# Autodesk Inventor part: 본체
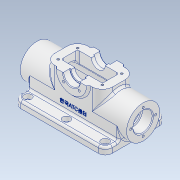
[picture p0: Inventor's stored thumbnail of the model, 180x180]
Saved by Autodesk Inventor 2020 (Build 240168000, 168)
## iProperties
Created: 2024-06
Part Number: 본체
Material: 알루미늄 6061
Document SubType Name: Modeling
Designer: oem
Density: 2.7 g/cm^3
Appearance: 알루미늄 - 평지
Mass: 551.511 g
Surface Area: 611.953 cm^2
Volume: 204.263 cm^3
Author: oem
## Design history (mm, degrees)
sketch "스케치3"
  geometry: L1 (0, 0)-(154, 0); L2 (0, 24)-(154, 24); L3 (0, 0)-(0, 24); L4 (154, 24)-(154, 0)
  constraints: 8 end point, 2 horizontal, 1 vertical
  dimensions: "d6" = 48 diameter of L2 L1; "d7" = 154 distance of L2.start L2.end; "d8" = 154 distance of L1.start L1.end
revolve "회전1" sketch "스케치3" stored, may be unused: angle "d9" = 90 deg
node "작업 평면1"
sketch "스케치4"
  geometry: L1 (-11, -44)-(-143, -44); L2 (-143, -44)-(-143, 44); L3 (-143, 44)-(-11, 44); L4 (-11, 44)-(-11, -44); L5 (0, -24)-(-154, -24) reference; 6 further points
  constraints: 8 end point, 3 midpoint, 2 parallel, 1 horizontal, 1 horizontal alignment, 1 perpendicular, 1 vertical alignment
  dimensions: "d11" = 132 distance of L1.start L1.end; "d12" = 88 distance of L3.end L1.start
extrude "돌출2" join sketch "스케치4" distance "d13" = 10; taper "d14" = 0 deg
node "작업 평면2"
sketch "스케치5"
  geometry: L1 (-35, -24)-(-119, -24); L2 (-119, -24)-(-119, 24); L3 (-119, 24)-(-35, 24); L4 (-35, 24)-(-35, -24); L5 (0, -24)-(-154, -24) reference; 6 further points
  constraints: 8 end point, 3 midpoint, 2 parallel, 1 coincident, 1 horizontal, 1 horizontal alignment, 1 perpendicular
  dimensions: "d16" = 84 distance of L1.start L1.end; "d17" = 48 distance of L3.end L1.start
extrude "돌출3" join sketch "스케치5" stored distance "d18" = 20; taper "d19" = 0 deg
sketch "스케치7"
  geometry: L1 (11, -15.875)-(11, -44) reference; L2 (143, -44)-(143, -15.875) reference; L3 (0, 24)-(154, 24) reference; L4 (0, -24)-(154, -24) reference; L5 (11, 44)-(11, -44) reference; L6 (143, -44)-(143, 44) reference; L7 (11, 24)-(143, 24); L8 (143, 24)-(143, -24); L9 (143, -24)-(11, -24); L10 (11, -24)-(11, 24); 4 further points
  constraints: 8 end point, 4 point on line, 2 parallel, 1 horizontal, 1 perpendicular
extrude "돌출5" join sketch "스케치7" stored distance "d28" = 10; taper "d29" = 0 deg
sketch "스케치9"
  geometry: L1 (119, 31)-(35, 31) reference; L2 (99, 31)-(55, 31); A1 r 22 centre (77, 31) between (99, 31) and (55, 31); 2 further points
  constraints: 2 end point, 2 point on circle, 2 point on line, 1 centre point, 1 coincident, 1 midpoint
  dimensions: "d33" = 44 diameter of A1
extrude "돌출7" join sketch "스케치9" stored distance "d34" = 54; taper "d35" = 0 deg
sketch "스케치10"
  geometry: L1 (55, 27)-(99, 27) reference; L2 (47, 12)-(107, 12); L3 (107, 12)-(107, -12); L4 (107, -12)-(47, -12); L5 (47, -12)-(47, 12); 4 further points
  constraints: 8 end point, 3 midpoint, 2 parallel, 1 horizontal, 1 horizontal alignment, 1 perpendicular, 1 vertical alignment
  dimensions: "d36" = 60 distance of L2.start L2.end; "d37" = 24 distance of L4.end L2.start
extrude "돌출8" cut sketch "스케치10" extent not by distance; stored distance "d38" = 0; taper "d39" = 0 deg
node "작업 평면3"
sketch "스케치11"
  geometry: L1 (9, -27)-(31, -27) reference; L2 (19, -27)-(19, -17); L3 (19, -17)-(21, -17); L4 (21, -17)-(21, 17); L5 (21, 17)-(19, 17); L6 (19, 17)-(19, 27); L7 (31, 27)-(9, 27) reference; L8 (31, -27)-(31, -24) reference; L9 (31, -27)-(31, 27); 2 further points
  constraints: 12 end point, 4 point on line, 3 perpendicular, 2 vertical
  dimensions: "d41" = 10 distance of L2.start L2.end; "d42" = 10 distance of L5.end L6.end; "d43" = 24 diameter of L6 L9; "d44" = 20 diameter of L4 L9
revolve "회전3" sketch "스케치11" stored, may be unused: angle "d45" = 90 deg
sketch "스케치12"
  geometry: L1 (0, -24)-(0, 24) reference; L2 (0, 14)-(15, 14); L3 (15, 14)-(15, 11); L4 (139, 11)-(139, 14); L5 (139, 14)-(154, 14); L6 (154, -24)-(154, 24) reference; L7 (0, 0)-(154, 0); L8 (15, 11)-(17, 11); L9 (17, 11)-(17, 18); L10 (17, 18)-(137, 18); L11 (137, 18)-(137, 11); L12 (137, 11)-(139, 11); A1 r 10 centre (77, 31) between (67, 31) and (87, 31) reference; 2 further points
  constraints: 20 end point, 5 perpendicular, 5 point on line, 2 horizontal, 2 midpoint, 1 point on circle, 1 vertical alignment
  dimensions: "d46" = 15 distance of L2.start L2.end; "d47" = 15 distance of L4.end L5.end; "d48" = 28 diameter of L2 L7; "d59" = 36 diameter of L10 L7; "d60" = 120 distance of L9.end L10.end; "d61" = 22 diameter of L12 L7
revolve "회전4" sketch "스케치12" stored, may be unused: angle "d50" = 90 deg
sketch "스케치13"
  geometry: L1 (107, 12)-(107, -12) reference; L2 (107, -12)-(47, -12) reference; L3 (47, -12)-(47, 12) reference; L4 (47, 12)-(107, 12) reference; L5 (11, -44)-(11, 44) reference; L6 (143, 44)-(143, -44) reference; L7 (17, 18)-(137, 18); L8 (137, 18)-(137, -18); L9 (137, -18)-(17, -18); L10 (17, -18)-(17, 18); L11 (143, 24)-(11, 24) reference; L12 (11, -24)-(143, -24) reference; 1 further point
  constraints: 8 end point, 2 parallel, 1 horizontal, 1 perpendicular
  dimensions: "d52" = 6 distance between parallel lines of L5 L10; "d54" = 6 distance between parallel lines of L6 L8; "d55" = 6 distance between parallel lines of L9 L12; "d56" = 6 distance between parallel lines of L11 L7
extrude "돌출9" cut sketch "스케치13" distance "d57" = 28; taper "d58" = 0 deg
fillet "모깎기1" dims "d62" = 10
sketch "스케치14"
  geometry: L1 (133, 44)-(21, 44) reference; A1 r 10 centre (21, 34) between (21, 44) and (11, 34) reference; A2 r 10 centre (133, 34) between (143, 34) and (133, 44) reference; A3 r 10 centre (21, -34) between (11, -34) and (21, -44) reference; A4 r 10 centre (133, -34) between (133, -44) and (143, -34) reference; 8 further points
  constraints: 4 coincident, 2 horizontal alignment, 2 vertical alignment, 1 midpoint
hole "구멍1" sketch "스케치14" at (133, 34), (77, 34), (21, 34), (21, -34), (77, -34), (133, -34) diameter "d63" = 6.6; stored, may be unused: countersink angle "d67" = 90 deg, drill point angle "d69" = 118 deg; dims "d64" = 11, "d65" = 11, "d66" = 6.6, "d68" = 8
sketch "스케치15"
  geometry: C1 r 14 at (0, 0) reference; C2 r 24 at (0, 0) reference; A1 r 18 centre (0, 0) between (0, 18) and (0, -18); 2 further points
  constraints: 3 point on circle, 2 vertical alignment, 1 centre point, 1 coincident, 1 horizontal alignment
  dimensions: "d70" = 36 diameter of A1
hole "구멍2" sketch "스케치15" at (0, 18), (0, -18), (18, 0), (-18, 0) diameter "d71" = 3.242; stored, may be unused: countersink angle "d75" = 82 deg, drill point angle "d77" = 118 deg; dims "d72" = 8, "d73" = 3.023, "d74" = 6.6, "d76" = 10
sketch "스케치16"
  geometry: C1 r 24 at (0, 0) reference; C2 r 1.621 at (0, -18) reference; A1 r 18 centre (0, 0) between (0, 18) and (18, 0); A2 r 18 centre (0, 0) between (18, 0) and (-18, 0) reference; 1 further point
  constraints: 2 coincident, 2 point on circle, 1 centre point
hole "구멍3" sketch "스케치16" at (0, 18), (18, 0), (0, -18), (-18, 0) diameter "d79" = 3.242; stored, may be unused: countersink angle "d83" = 82 deg, drill point angle "d85" = 118 deg; dims "d80" = 8, "d81" = 3.023, "d82" = 6.6, "d84" = 10
fillet "모깎기2" dims "d86" = 15
sketch "스케치17"
  geometry: L1 (45, -14)-(109, -14); L2 (109, -14)-(109, 14); L3 (109, 14)-(45, 14); L4 (45, 14)-(45, -14); L5 (65, 27)-(89, 27) reference; A1 r 15 centre (50, -9) between (35, -9) and (50, -24) reference; A2 r 15 centre (50, 9) between (50, 24) and (35, 9) reference; 8 further points
  constraints: 8 end point, 4 coincident, 3 midpoint, 2 parallel, 1 horizontal, 1 horizontal alignment, 1 perpendicular, 1 vertical alignment
  dimensions: "d87" = 64 distance of L2.end L3.end; "d88" = 28 distance of L3.end L1.start
fillet "모깎기3" dims "d89" = 3
hole "구멍4" sketch "스케치17" diameter "d90" = 3.242; stored, may be unused: countersink angle "d94" = 82 deg, drill point angle "d96" = 118 deg; dims "d91" = 8, "d92" = 3.023, "d93" = 6.6, "d95" = 10
sketch "스케치18"
  geometry: L1 (-77, 31)-(-77, 15); L2 (-77, 31)-(-88.314, 19.686); L3 (-77, 31)-(-65.686, 19.686); A1 r 22 centre (-77, 31) between (-99, 31) and (-55, 31) reference; A2 r 16 centre (-77, 31) between (-88.314, 19.686) and (-65.686, 19.686); 1 further point
  constraints: 6 end point, 3 point on circle, 1 centre point, 1 coincident, 1 vertical
  dimensions: "d97" = 32 diameter of A2; "d98" = 45 deg angle of L2 L1; "d99" = 45 deg angle of L3 L1
hole "구멍5" sketch "스케치18" at (-88.314, 19.686), (-65.686, 19.686) diameter "d100" = 3.242; stored, may be unused: countersink angle "d104" = 82 deg, drill point angle "d106" = 118 deg; dims "d101" = 8, "d102" = 3.023, "d103" = 6.6, "d105" = 10
sketch "스케치19"
  geometry: L1 (65.686, 19.686)-(77, 31); L2 (77, 31)-(88.314, 19.686); L3 (77, 31)-(77, 15); A1 r 22 centre (77, 31) between (55, 31) and (99, 31) reference; A2 r 16 centre (77, 31) between (65.686, 19.686) and (88.314, 19.686); 1 further point
  constraints: 6 end point, 3 point on circle, 1 centre point, 1 coincident, 1 vertical
  dimensions: "d107" = 32 diameter of A2; "d108" = 45 deg angle of L2 L3; "d109" = 45 deg angle of L1 L3
hole "구멍6" sketch "스케치19" at (65.686, 19.686), (88.314, 19.686) diameter "d110" = 3.242; stored, may be unused: countersink angle "d114" = 82 deg, drill point angle "d116" = 118 deg; dims "d111" = 8, "d112" = 3.023, "d113" = 6.6, "d115" = 10
fillet "모깎기4" dims "d117" = 0.3
fillet "모깎기5" dims "d118" = 3
fillet "모깎기6" dims "d119" = 3
fillet "모깎기7" dims "d120" = 3
fillet "모깎기8" dims "d121" = 3
chamfer "모따기1" distance "d122" = 1; stored, may be unused: second distance "d123" = 2, angle "d124" = 45 deg
chamfer "모따기2" distance "d125" = 1; stored, may be unused: second distance "d126" = 2, angle "d127" = 45 deg
fillet "모깎기9" dims "d128" = 3
fillet "모깎기10" dims "d129" = 3
sketch "스케치20"
  geometry: L1 (7, -13)-(119, -13) reference; A1 r 25 centre (63, 46) between (38, 46) and (88, 46) reference; 2 further points
  constraints: 1 vertical alignment, 1 other
  dimensions: "d130" = 20 distance from line of L1 point (63, 7)
feature "엠보싱1" sketch "스케치20" dims "d6" = 48, "d7" = 154, "d8" = 154, "d16" = 84, "d17" = 48, "d131" = 0.5, "d132" = 0
fillet "모깎기11" dims "d133" = 3
node "솔리드2"
feature "A9D066F2-1C7D-4E18-AEED-F7BC21143FA4" dims "d63" = 6.6, "d64" = 11, "d65" = 11, "d66" = 6.6, "d67" = 90 deg, "d68" = 8, "d69" = 118 deg
other parameters: "d10" = -28, "d15" = 31, "d40" = 77
